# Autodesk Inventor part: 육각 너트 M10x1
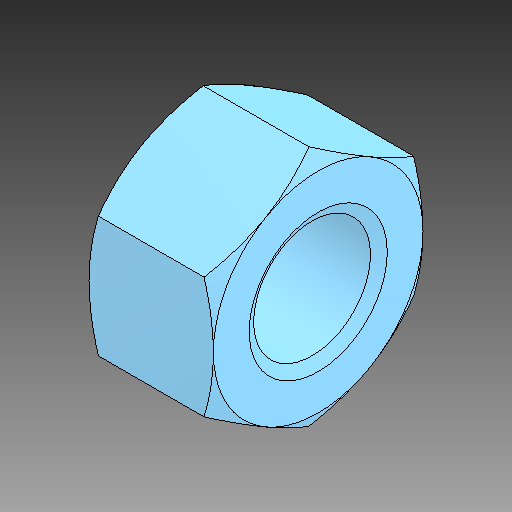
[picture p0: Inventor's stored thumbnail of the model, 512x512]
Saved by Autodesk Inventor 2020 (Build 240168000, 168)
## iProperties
Created: 2024-08
Part Number: 육각 너트 M10x1
Material: 강철, 연강
Description: 6각 너트 및 6각 가는 너트
Document SubType Name: Modeling
Designer: 1강의실14
Density: 7.85 g/cm^3
Appearance: 기본값
Author: jhkim
Sending System: Autodesk Inventor 2025
Preprocessor: ST-DEVELOPER v20
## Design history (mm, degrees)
feature "Solid1"
node "솔리드1"
